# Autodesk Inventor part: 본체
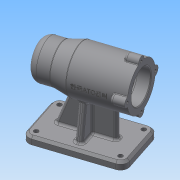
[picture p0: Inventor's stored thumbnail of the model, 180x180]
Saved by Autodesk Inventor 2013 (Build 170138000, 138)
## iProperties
Created: 2019-07
Part Number: 본체
Material: 알루미늄 6061
Document SubType Name: Modeling
Designer: Administrator
Density: 2.71 g/cm^3
Mass: 645.344 g
Surface Area: 653.867 cm^2
Volume: 238.134 cm^3
Author: Administrator
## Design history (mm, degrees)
sketch "스케치1"
  geometry: L1 (-56, 35)-(56, 35); L2 (56, 35)-(56, -35); L3 (56, -35)-(-56, -35); L4 (-56, -35)-(-56, 35); L5 (-56, 35)-(56, -35); L6 (56, 35)-(-56, -35); 1 further point
  constraints: 12 end point, 2 midpoint, 2 parallel, 1 horizontal, 1 perpendicular
  dimensions: "d0" = 112 distance of L2.end L3.end; "d1" = 70 distance of L1.end L2.end
extrude "돌출1" new body sketch "스케치1" distance "d2" = 10; taper "d3" = 0 deg
sketch "스케치2"
  geometry: L1 (-56, 80)-(-56, 105); L2 (-56, 105)-(-31, 105); L3 (-31, 105)-(-11, 110); L4 (-11, 110)-(56, 110); L5 (56, 110)-(56, 80); L6 (56, 80)-(-56, 80); L7 (-56, 0)-(56, 0) reference; 3 further points
  constraints: 12 end point, 3 parallel, 2 midpoint, 1 perpendicular, 1 vertical, 1 vertical alignment
  dimensions: "d4" = 50 diameter of L2 L6; "d6" = 60 diameter of L4 L6; "d7" = 112 distance of L5.end L1.start; "d8" = 80 distance between parallel lines of L7 L6; "d9" = 25 distance of L1.end L2.end; "d10" = 45 distance from line of L3.end L1
revolve "회전1" sketch "스케치2" stored, may be unused: angle "d11" = 90 deg
sketch "스케치3"
  geometry: L1 (56, 50)-(56, 110) reference; L2 (-56, 55)-(-56, 105) reference; L3 (56, 80)-(-56, 80); L4 (56, 101)-(41, 101); L5 (41, 101)-(41, 104); L6 (41, 104)-(-13, 104); L7 (-13, 104)-(-13, 101); L8 (-13, 101)-(-25, 101); L9 (-25, 101)-(-25, 97.5); L10 (-25, 97.5)-(-43, 97.5); L11 (-43, 97.5)-(-43, 96); L12 (-43, 96)-(-47, 96); L13 (56, 101)-(56, 80); L14 (-47, 90.5)-(-50, 90.5); L15 (-50, 90.5)-(-50, 80); L16 (-47, 96)-(-47, 90.5); 2 further points
  constraints: 28 end point, 8 parallel, 3 midpoint, 3 perpendicular, 2 collinear, 1 point on line, 1 vertical alignment
  dimensions: "d12" = 15 distance of L4.start L4.end; "d14" = 54 distance of L5.end L6.end; "d15" = 12 distance of L7.end L8.end; "d16" = 18 distance of L9.end L10.end; "d17" = 4 distance of L11.end L12.end; "d18" = 3 distance of L14.start L14.end; "d19" = 42 diameter of L4 L3; "d20" = 48 diameter of L6 L3; "d21" = 21 diameter of L14 L3; "d22" = 32 diameter of L12 L3; "d23" = 35 diameter of L10 L3; "d24" = 42 diameter of L8 L3
revolve "회전2" sketch "스케치3" stored, may be unused: angle "d25" = 90 deg
sketch "스케치4"
  geometry: L1 (56, -35)-(56, 35) reference; L2 (-31, 4)-(36, 4); L3 (36, 4)-(36, -4); L4 (36, -4)-(-31, -4); L5 (-31, -4)-(-31, 4); L6 (-56, 35)-(-56, -35) reference; 2 further points
  constraints: 8 end point, 2 parallel, 1 horizontal, 1 horizontal alignment, 1 midpoint, 1 perpendicular
  dimensions: "d29" = 8 distance of L4.end L2.start; "d102" = 25 distance between parallel lines of L6 L5; "d103" = 20 distance between parallel lines of L1 L3
extrude "돌출2" join sketch "스케치4" stored distance "d33" = 10; taper "d34" = 0 deg
feature "면 기울기1" dims angle "d35" = 20 deg
sketch "스케치6"
  geometry: C1 r 21 at (0, 0) reference; C2 r 6 at (0, 30); 1 further point
  constraints: 1 centre point, 1 vertical alignment
  dimensions: "d44" = 12 diameter of C2; "d45" = 30 distance of C2.centre C1.centre
extrude "돌출4" join sketch "스케치6" distance "d46" = 16; taper "d47" = 0 deg
sketch "스케치7"
  geometry: A1 r 6 centre (0, 0) between (5.97, -0.6) and (-5.97, -0.6) reference; 2 further points
  constraints: 1 coincident
hole "구멍1" sketch "스케치7" at (0, 0) diameter "d48" = 3.459; stored, may be unused: countersink angle "d52" = 90 deg, drill point angle "d54" = 118 deg; dims "d49" = 8, "d50" = 4, "d51" = 2, "d53" = 11
fillet "모깎기1" dims "d58" = 10
sketch "스케치8"
  geometry: A1 r 10 centre (46, -25) between (46, -35) and (56, -25) reference; A2 r 10 centre (46, 25) between (56, 25) and (46, 35) reference; A3 r 10 centre (-46, 25) between (-46, 35) and (-56, 25) reference; A4 r 10 centre (-46, -25) between (-56, -25) and (-46, -35) reference; 5 further points
  constraints: 4 coincident
hole "구멍2" sketch "스케치8" at (-46, 25), (-46, -25), (46, 25), (46, -25) diameter "d59" = 6; stored, may be unused: countersink angle "d63" = 90 deg, drill point angle "d65" = 0 deg; dims "d60" = 8, "d61" = 4, "d62" = 2, "d64" = 11
chamfer "모따기1" distance "d66" = 3; stored, may be unused: second distance "d67" = 2, angle "d68" = 45 deg
fillet "모깎기8" dims "d75" = 10
fillet "모깎기9" dims "d76" = 3
sketch "스케치9"
  geometry: L1 (-46, 32)-(46, 32) reference; L2 (46, -32)-(-46, -32) reference; L3 (-4, 25)-(4, 25); L4 (4, 25)-(4, -25); L5 (4, -25)-(-4, -25); L6 (-4, -25)-(-4, 25); 2 further points
  constraints: 8 end point, 2 parallel, 1 horizontal, 1 midpoint, 1 perpendicular, 1 vertical alignment
  dimensions: "d77" = 8 distance of L3.start L3.end; "d79" = 7 distance between parallel lines of L1 L3; "d80" = 7 distance between parallel lines of L2 L5
extrude "돌출5" join sketch "스케치9" stored distance "d81" = 16; taper "d82" = 0 deg
feature "면 기울기4" dims angle "d83" = 10 deg
fillet "모깎기10" dims "d84" = 3
fillet "모깎기11" dims "d85" = 3
fillet "모깎기12" dims "d86" = 3
fillet "모깎기13" dims "d87" = 3
chamfer "모따기2" distance "d88" = 1; stored, may be unused: second distance "d89" = 2, angle "d90" = 45 deg
fillet "모깎기14" dims "d91" = 0.3
fillet "모깎기15" dims "d96" = 3
fillet "모깎기16" dims "d97" = 1
node "작업 평면2"
sketch "스케치11"
  geometry: L1 (33.5, 36)-(33.5, 30.171) reference; L2 (-33.131, 30)-(16.5, 30) reference; 2 further points
  constraints: 1 other
  dimensions: "d98" = 42 distance from line of point (-8.5, 0) L1; "d99" = 30 distance from line of point (-8.5, 0) L2
feature "엠보싱2" sketch "스케치11" dims "d0" = 112, "d1" = 70, "d100" = 0.5, "d101" = 0
node "솔리드1"
pattern_circular "원형 패턴1" dims angle "d56" = 360 deg
